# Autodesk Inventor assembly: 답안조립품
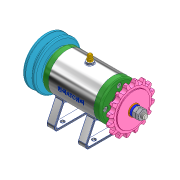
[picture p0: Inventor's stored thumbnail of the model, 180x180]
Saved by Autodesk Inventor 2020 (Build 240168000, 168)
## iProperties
Created: 2021-12
Part Number: 답안조립품
Document SubType Name: Assembly
Designer: MIRAE
Author: MIRAE
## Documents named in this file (16)
- C:\Users\MIRAE\Desktop\711206V1009\답안조립품.iam
- C:\Users\MIRAE\Desktop\711206V1009\본체.ipt
- C:\Users\MIRAE\Desktop\711206V1009\축.ipt
- C:\Users\MIRAE\Desktop\711206V1009\베어링 6002.ipt
- C:\Users\MIRAE\Desktop\711206V1009\커버.ipt
- C:\Users\MIRAE\Desktop\711206V1009\볼트 M4 x 12.ipt
- C:\Users\MIRAE\Desktop\711206V1009\오일 실 15 x 25 x 7.ipt
- C:\Users\MIRAE\Desktop\711206V1009\키 3 x 3.ipt
- C:\Users\MIRAE\Desktop\711206V1009\V벨트풀리.ipt
- C:\Users\MIRAE\Desktop\711206V1009\스프로킷.ipt
- C:\Users\MIRAE\Desktop\711206V1009\와셔 6 x 11.5.ipt
- C:\Users\MIRAE\Desktop\711206V1009\볼트 M6 x 8.ipt
- C:\Users\MIRAE\Desktop\711206V1009\니플 M6 x 0.75.ipt
- C:\Users\MIRAE\Desktop\711206V1009\와셔 8 x 17.ipt
- C:\Users\MIRAE\Desktop\711206V1009\스프링와셔 8.ipt
- C:\Users\MIRAE\Desktop\711206V1009\너트 M8.ipt
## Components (11 placed, 3 different names)
1. KS B 2023 6002 - 15 x 32 x 9:1
2. KS B 2023 6002 - 15 x 32 x 9:2
3. ISO 4762 M4 x 12:1
4. ISO 4762 M4 x 12:2
5. ISO 4762 M4 x 12:3
6. ISO 4762 M4 x 12:4
7. ISO 4762 M4 x 12:5
8. ISO 4762 M4 x 12:6
9. ISO 4762 M4 x 12:7
10. ISO 4762 M4 x 12:8
11. V벨트풀리:1 — 각도:3
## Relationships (1: Angle 1)
- 각도:3 [Angle]: V벨트풀리:1
